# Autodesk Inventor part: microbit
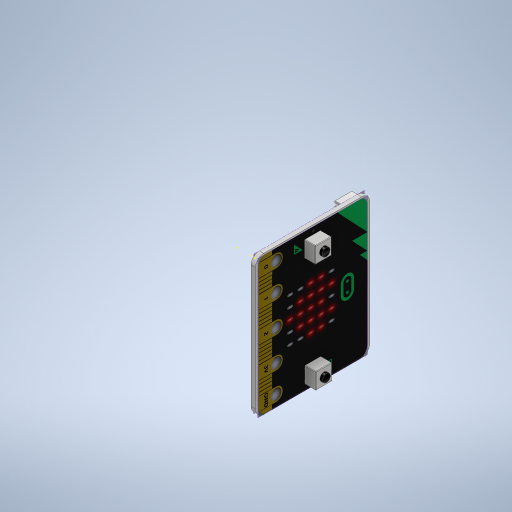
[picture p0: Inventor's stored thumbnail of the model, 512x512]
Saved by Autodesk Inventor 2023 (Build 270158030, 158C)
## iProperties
Part Number: microbit
Material: Générique
Document SubType Name: Modeling
Designer: Buhl
Density: 1 g/cm^3
Appearance: Par défaut
Author: Buhl
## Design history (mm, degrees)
sketch "Esquisse1"
  geometry: L1 (3, 0)-(39, 0); L2 (42, -3)-(42, -48); L3 (39, -51)-(3, -51); L4 (0, -48)-(0, -3); A1 r 2 centre (40, -49) between (40, -51) and (42, -49); A2 r 2 centre (40, -2) between (42, -2) and (40, 0); A3 r 3 centre (39, -48) between (39, -51) and (42, -48); A4 r 3 centre (39, -3) between (42, -3) and (39, 0); A5 r 3 centre (3, -3) between (3, 0) and (0, -3); A6 r 3 centre (3, -48) between (0, -48) and (3, -51); 4 further points
  constraints: 12 point on circle, 12 point on line, 12 tangent, 8 end point, 6 centre point, 4 equal radius, 2 parallel, 1 horizontal, 1 perpendicular
  dimensions: "d0" = 42 distance of point (42, -51) point (0, -51); "d1" = 51 distance of point (42, 0) point (42, -51); "d2" = 2 radius of A1 (derived); "d3" = 3 radius of A3
extrude "Extrusion1" new body sketch "Esquisse1" distance "d4" = 1.6; taper "d5" = 0 deg
sketch "Esquisse2"
  geometry: L1 (0.566, 41.203)-(51.277, 41.203); L2 (51.277, 41.203)-(51.277, 0.803); L3 (51.277, 0.803)-(0.566, 0.803); L4 (0.566, 0.803)-(0.566, 41.203); 1 further point; 1 other entity
  constraints: 2 other
  node "Image1"
sketch "Esquisse3"
  geometry: L1 (-50.817, 41.619)-(-0.018, 41.619); L2 (-0.018, 41.619)-(-0.018, 0.936); L3 (-0.018, 0.936)-(-50.817, 0.936); L4 (-50.817, 0.936)-(-50.817, 41.619); 1 further point; 1 other entity
  constraints: 2 other
  node "Image2"
sketch "Esquisse4"
  geometry: L1 (3.141, 24.01)-(9.141, 24.01); L2 (9.141, 24.01)-(9.141, 18.01); L3 (9.141, 18.01)-(3.141, 18.01); L4 (3.141, 18.01)-(3.141, 24.01); 1 further point
  constraints: 8 end point, 2 parallel, 1 horizontal, 1 perpendicular
  dimensions: "d40" = 6 distance of L2.end L3.end; "d41" = 6 distance of L1.end L2.end
extrude "Extrusion2" join sketch "Esquisse4" distance "d42" = 4; taper "d43" = 0 deg
fillet "Congé1" dims "d46" = 0.2
fillet "Congé2" dims "d47" = 0.2
sketch "Esquisse5"
  geometry: L1 (3.341, 18.21)-(3.341, 23.81) reference; L2 (8.941, 23.81)-(8.941, 18.21) reference; L3 (3.341, 23.81)-(8.941, 23.81) reference; C1 r 1.5 at (6.141, 21.01); 1 further point
  constraints: 1 centre point
  dimensions: "d48" = 3 diameter of C1
extrude "Extrusion3" join sketch "Esquisse5" distance "d49" = 1; taper "d50" = 0 deg
fillet "Congé3" dims "d51" = 0.1
sketch "Esquisse6"
  geometry: L1 (43.242, 24.154)-(49.242, 24.154); L2 (49.242, 24.154)-(49.242, 18.154); L3 (49.242, 18.154)-(43.242, 18.154); L4 (43.242, 18.154)-(43.242, 24.154); 1 further point
  constraints: 8 end point, 2 parallel, 1 horizontal, 1 perpendicular
  dimensions: "d52" = 6 distance of L2.end L3.end; "d53" = 6 distance of L1.end L2.end
extrude "Extrusion4" join sketch "Esquisse6" distance "d54" = 4; taper "d55" = 0 deg
fillet "Congé4" dims "d56" = 0.2
fillet "Congé5" dims "d57" = 0.2
sketch "Esquisse7"
  geometry: L1 (49.042, 23.954)-(49.042, 18.354) reference; L2 (49.042, 23.954)-(49.242, 23.954) reference; L3 (43.442, 18.354)-(43.442, 23.954) reference; C1 r 1.5 at (46.242, 21.154); A1 r 0.2 centre (43.442, 23.954) between (43.442, 24.154) and (43.242, 23.954) reference; 1 further point
  constraints: 1 centre point
  dimensions: "d58" = 3 diameter of C1
extrude "Extrusion5" join sketch "Esquisse7" distance "d59" = 1; taper "d60" = 0 deg
fillet "Congé6" dims "d61" = 0.1
sketch "Esquisse8"
  geometry: L1 (-12.86, 35.794)-(-18.86, 35.794); L2 (-18.86, 35.794)-(-18.86, 41.794); L3 (-18.86, 41.794)-(-12.86, 41.794); L4 (-12.86, 41.794)-(-12.86, 35.794); L5 (-12.86, 35.794)-(-18.86, 41.794); L6 (-18.86, 35.794)-(-12.86, 41.794); 2 further points
  constraints: 12 end point, 2 midpoint, 2 parallel, 1 horizontal, 1 perpendicular
  dimensions: "d62" = 6 distance of L2.end L3.end; "d63" = 6 distance of L1.end L2.end
extrude "Extrusion6" join sketch "Esquisse8" distance "d64" = 4; taper "d65" = 0 deg
fillet "Congé7" dims "d66" = 0.2
fillet "Congé8" dims "d67" = 0.2
sketch "Esquisse9"
  geometry: L1 (-18.66, 35.994)-(-18.66, 41.594) reference; L2 (-13.06, 35.994)-(-18.66, 35.994) reference; L3 (-18.66, 41.594)-(-13.06, 41.594) reference; C1 r 1.5 at (-15.86, 38.794); 1 further point
  constraints: 1 centre point
  dimensions: "d68" = 3 diameter of C1
extrude "Extrusion7" join sketch "Esquisse9" distance "d69" = 1; taper "d70" = 0 deg
fillet "Congé9" dims "d71" = 0.1
sketch "Esquisse10"
  geometry: L1 (-28.891, 38.196)-(-21.891, 38.196) reference; L2 (-21.891, 38.196)-(-21.891, 42.696); L3 (-21.891, 42.696)-(-28.891, 42.696); L4 (-28.891, 42.696)-(-28.891, 38.196); 1 further point
  constraints: 8 end point, 2 horizontal, 2 parallel, 1 perpendicular
  dimensions: "d72" = 7 distance of L3.end L2.end; "d73" = 4.5 distance of L2.end L1.end
extrude "Extrusion8" join sketch "Esquisse10" distance "d74" = 3; taper "d75" = 0 deg
sketch "Esquisse14"
  geometry: L1 (-43.375, 33.249)-(-37.775, 33.249); L2 (-37.775, 33.249)-(-37.775, 27.649); L3 (-37.775, 27.649)-(-43.375, 27.649); L4 (-43.375, 27.649)-(-43.375, 33.249); 1 further point
  constraints: 8 end point, 2 parallel, 1 horizontal, 1 perpendicular
  dimensions: "d83" = 5.6 distance of L2.end L3.end; "d84" = 5.6 distance of L1.end L2.end
extrude "Extrusion11" join sketch "Esquisse14" distance "d85" = 1; taper "d86" = 0 deg
sketch "Esquisse15"
  geometry: L1 (-13.681, 30.417)-(-9.181, 30.417); L2 (-9.181, 30.417)-(-9.181, 25.917); L3 (-9.181, 25.917)-(-13.681, 25.917); L4 (-13.681, 25.917)-(-13.681, 30.417); 1 further point
  constraints: 8 end point, 2 parallel, 1 horizontal, 1 perpendicular
  dimensions: "d87" = 4.5 distance of L2.end L3.end; "d88" = 4.5 distance of L1.end L2.end
extrude "Extrusion12" join sketch "Esquisse15" distance "d89" = 1; taper "d90" = 0 deg
sketch "Esquisse16"
  geometry: L1 (-47.39, 18.329)-(-45.19, 18.329); L2 (-45.19, 18.329)-(-45.19, 16.129); L3 (-45.19, 16.129)-(-47.39, 16.129); L4 (-47.39, 16.129)-(-47.39, 18.329); 1 further point
  constraints: 8 end point, 2 parallel, 1 horizontal, 1 perpendicular
  dimensions: "d91" = 2.2 distance of L2.end L3.end; "d92" = 2.2 distance of L1.end L2.end
extrude "Extrusion13" join sketch "Esquisse16" distance "d93" = 1; taper "d94" = 0 deg
sketch "Esquisse17"
  geometry: L1 (-11.005, 35.782)-(-3.005, 35.782); L2 (-3.005, 35.782)-(-3.005, 41.982); L3 (-3.005, 41.982)-(-11.005, 41.982); L4 (-11.005, 41.982)-(-11.005, 35.782); 1 further point
  constraints: 8 end point, 2 parallel, 1 horizontal, 1 perpendicular
  dimensions: "d95" = 8 distance of L3.end L2.end; "d96" = 6.2 distance of L2.end L1.end
extrude "Extrusion14" join sketch "Esquisse17" distance "d97" = 5; taper "d98" = 0 deg
sketch "Esquisse18"
  geometry: L1 (-0.75, 0.75)-(-4.25, 0.75); L2 (-4.25, 0.75)-(-4.25, 7.25); L3 (-4.25, 7.25)-(-0.75, 7.25); L4 (-0.75, 7.25)-(-0.75, 0.75); 1 further point
  constraints: 8 end point, 2 parallel, 1 horizontal, 1 perpendicular
  dimensions: "d99" = 3.5 distance of L2.end L3.end; "d100" = 6.5 distance of L1.end L2.end
extrude "Extrusion15" cut sketch "Esquisse18" distance "d101" = 5; taper "d102" = 0 deg
sketch "Esquisse19"
  geometry: L1 (-3.644, 34.795)-(-4.644, 34.795); L2 (-4.644, 34.795)-(-4.644, 38.795); L3 (-4.644, 38.795)-(-3.644, 38.795) reference; L4 (-3.644, 38.795)-(-3.644, 34.795); 1 further point
  constraints: 8 end point, 2 horizontal, 2 parallel, 1 perpendicular
  dimensions: "d103" = 1 distance of L2.end L3.end; "d104" = 4 distance of L1.end L2.end
extrude "Extrusion16" cut sketch "Esquisse19" distance "d105" = 2; taper "d106" = 0 deg
sketch "Esquisse20"
  geometry: 1 further point
sketch "Esquisse21"
  geometry: L1 (-11.005, 35.782)-(-3.005, 35.782) reference; L2 (-10.249, 35.782)-(-9.249, 35.782); L3 (-9.249, 35.782)-(-9.249, 38.782); L4 (-9.249, 38.782)-(-10.249, 38.782); L5 (-10.249, 38.782)-(-10.249, 35.782); 2 further points
  constraints: 8 end point, 2 parallel, 1 horizontal, 1 perpendicular, 1 point on line
  dimensions: "d107" = 1 distance of L4.end L3.end; "d108" = 3 distance of L3.end L2.end
extrude "Extrusion17" cut sketch "Esquisse21" distance "d109" = 2; taper "d110" = 0 deg
sketch "Esquisse22"
  geometry: L1 (-13.681, 30.417)-(-9.181, 30.417) reference; L2 (-9.181, 25.917)-(-13.681, 25.917) reference; L3 (-13.681, 30.417)-(-9.181, 30.417); L4 (-9.181, 30.417)-(-9.181, 25.917); L5 (-9.181, 25.917)-(-13.681, 25.917); L6 (-13.681, 25.917)-(-13.681, 30.417); 3 further points
  constraints: 8 end point, 2 parallel, 1 horizontal, 1 perpendicular
extrude "Extrusion18" join sketch "Esquisse22" distance "d111" = 1; taper "d112" = 0 deg
fillet "Congé11" dims "d113" = 1
sketch "Esquisse23"
  geometry: L1 (-2, -0.5)-(-1, -0.5); L2 (-0.5, 0)-(-0.5, 5); L3 (-1, 5.5)-(-2, 5.5); L4 (-2.5, 5)-(-2.5, 0); L5 (-2.5, -0.5)-(-0.5, 5.5); L6 (-0.5, -0.5)-(-2.5, 5.5); A1 r 1 centre (-1, 5) between (0, 5) and (-1, 6) reference; A2 r 1 centre (-2, 0) between (-3, 0) and (-2, -1) reference; A3 r 1 centre (-2, 5) between (-2, 6) and (-3, 5) reference; A4 r 1 centre (-1, 0) between (-1, -1) and (0, 0) reference; A5 r 0.5 centre (-1, 5) between (-0.5, 5) and (-1, 5.5); A6 r 0.5 centre (-1, 0) between (-1, -0.5) and (-0.5, 0); A7 r 0.5 centre (-2, 0) between (-2.5, 0) and (-2, -0.5); A8 r 0.5 centre (-2, 5) between (-2, 5.5) and (-2.5, 5); 8 further points
  constraints: 12 end point, 10 point on circle, 8 point on line, 8 tangent, 4 centre point, 4 coincident, 3 equal radius, 2 midpoint, 2 parallel, 1 horizontal, 1 perpendicular
  dimensions: "d114" = 2 distance of L6.end L5.end; "d115" = 6 distance of L5.end L6.start; "d116" = 0.5 radius of A5 (derived)
extrude "Extrusion19" cut sketch "Esquisse23" distance "d117" = 3.5; taper "d118" = 0 deg
sketch "Esquisse24"
  geometry: L1 (-1.5, 1)-(-0.9, 1); L2 (-0.9, 1)-(-0.9, 6); L3 (-0.9, 6)-(-1.5, 6); L4 (-2, 5.5)-(-2, 1.5); A1 r 1 centre (-2, 1) between (-3, 1) and (-2, 0) reference; A2 r 0.5 centre (-2, 6) between (-2, 6.5) and (-2.5, 6) reference; A3 r 0.5 centre (-2, 1) between (-2.5, 1) and (-2, 0.5) reference; A4 r 0.5 centre (-2, 1) between (-2, 1.5) and (-1.5, 1); A5 r 0.5 centre (-2, 6) between (-1.5, 6) and (-2, 5.5); 9 further points
  constraints: 8 end point, 5 point on circle, 3 coincident, 2 centre point, 2 parallel, 1 horizontal, 1 perpendicular
  dimensions: "d119" = 0.6 distance of L3.end L2.end; "d120" = 1 diameter of A4; "d121" = 1 diameter of A5
extrude "Extrusion20" cut sketch "Esquisse24" extent not by distance; stored distance "d122" = 0; taper "d123" = 0 deg
node "Solide1"
